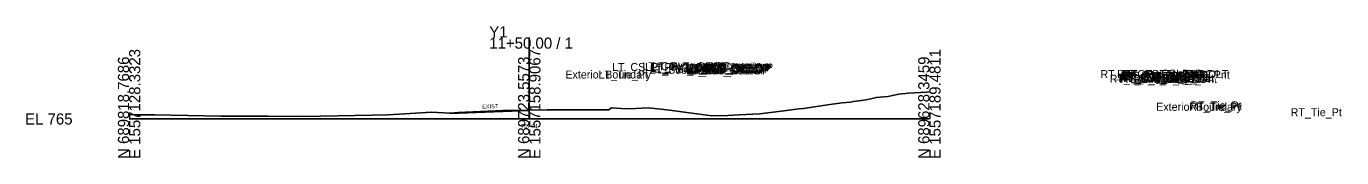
# Model space of a CAD drawing. Extents: x -26 to 303, y -10 to 5005.
# Drawn here: x -25.7 to 303, y 1490.3 to 1523.2 of the extents above; entities that cross this region are included whole.
import ezdxf

# ---------------------------------------------------------------- set-up
doc = ezdxf.new("R2010")
doc.units = 0
for name, color, linetype in [('Default', 7, 'Continuous'), ('Exist Cross Section Cell', 7, 'Continuous'), ('Exist XS Center Line Elevation Label', 7, 'Continuous'), ('Exist XS Ground Line', 7, 'Continuous'), ('Prop CMT Pvmt Course 1', 7, 'Continuous'), ('Prop CMT Pvmt Surface', 7, 'Continuous'), ('Prop XS SE Text', 7, 'Continuous')]:
    doc.layers.add(name, color=color, linetype=linetype)

msp = doc.modelspace()

# ---------------------------------------------------------------- linework, layer by layer
at = {"layer": 'Exist Cross Section Cell'}
for p, q in [((100, 1500), (100, 1520.37)), ((0, 1500), (100, 1500)), ((100, 1500), (200, 1500))]:
    msp.add_line(p, q, dxfattribs=at)
at = {"layer": 'Exist XS Ground Line'}
msp.add_lwpolyline([(0, 1501.08), (1.84, 1501.07), (3.01, 1501.07), (6.4, 1501), (22.89, 1500.72), (34.77, 1500.7), (43.56, 1500.61), (60.66, 1500.97), (64.57, 1501), (67.56, 1501.18), (75.54, 1501.67), (80.14, 1501.48), (82.23, 1501.65), (93.39, 1502.08), (93.84, 1502.1), (100, 1502.21), (104.44, 1502.28), (105.78, 1502.31), (118.02, 1502.3), (118.86, 1502.3), (119.88, 1502.3), (120.53, 1502.77), (124.21, 1502.57), (126.57, 1502.65), (129.69, 1502.81), (133.66, 1502.36), (135.67, 1502.14), (139.37, 1501.62), (145.59, 1500.74), (149.64, 1500.88), (152.45, 1501.06), (157.63, 1501.27), (164.28, 1502.14), (167.39, 1502.57), (168.56, 1502.64), (175.13, 1503.58), (178.19, 1504.02), (180.29, 1504.23), (181.02, 1504.37), (183.01, 1504.62), (184.62, 1504.88), (186.74, 1505.37), (188.61, 1505.55), (189.67, 1505.63), (190.77, 1505.9), (192.39, 1506.23), (193.11, 1506.3), (193.99, 1506.33), (194.81, 1506.43), (199.35, 1506.71), (200, 1506.79)], dxfattribs=at)
at = {"layer": 'Prop CMT Pvmt Course 1'}
for p, q in [((80.14, 1501.35), (100, 1502.08)), ((80.14, 1501.48), (80.14, 1501.35))]:
    msp.add_line(p, q, dxfattribs=at)
for points in [[(100, 1502.21), (100, 1502.08)], [(100, 1502.08), (100, 1502.21)]]:
    msp.add_lwpolyline(points, dxfattribs=at)
at = {"layer": 'Prop CMT Pvmt Surface'}
msp.add_line((80.14, 1501.48), (100, 1502.21), dxfattribs=at)

# ---------------------------------------------------------------- texts
at = {"layer": 'Default'}
for s, height, p in [('Exterior Boundary', 2, (109.02, 1510.11)), ('LT_Tie_Pt', 2, (117.32, 1510.11)), ('LT_CSLP_Pnt', 2, (120.67, 1511.99)), ('LT_CG_Top_BOC', 2, (128.28, 1512.18)), ('LT_Sub_OEOT', 2, (130.08, 1511.3)), ('LT_PV2_OEOT', 2, (130.17, 1511.93)), ('LT_PV3_OEOT', 2, (130.17, 1511.68)), ('LT_PV1_OEOT', 2, (130.74, 1512.18)), ('RT_Sub_OEEOP', 2, (139.17, 1511.15)), ('LT_Sub_OEEOP', 2, (139.21, 1511.15)), ('RT_PV2_OEEOP', 2, (139.26, 1511.78)), ('RT_PV3_OEEOP', 2, (139.26, 1511.53)), ('LT_PV2_OEEOP', 2, (139.31, 1511.78)), ('LT_PV3_OEEOP', 2, (139.31, 1511.53)), ('RT_PV1_OEEOP', 2, (139.83, 1511.9)), ('LT_PV1_OEEOP', 2, (139.87, 1511.9)), ('RT_PV2_IEEOP', 2, (139.91, 1511.78)), ('LT_PV2_IEEOP', 2, (139.95, 1511.78)), ('RT_PV1_IEEOP', 2, (140.47, 1511.9)), ('LT_PV1_IEEOP', 2, (140.52, 1511.9)), ('RT_PV2_PGL', 2, (141.17, 1511.78)), ('LT_PV2_PGL', 2, (141.21, 1511.78)), ('RT_PV1_PGL', 2, (141.73, 1512.03)), ('LT_PV1_PGL', 2, (141.78, 1512.03)), ('RT_Sub_Trench_Out_DLT', 2, (242.73, 1510.21)), ('RT_CG_Top_Face', 2, (246.93, 1510.25)), ('RT_CG_Top_BOC', 2, (248.45, 1510.25)), ('CSLP_Pnt', 2, (257.92, 1510.33)), ('RT_Sub_OEOT_CG', 2, (245.04, 1509.04)), ('RT_CG1_Shelf_Out', 2, (247.22, 1509.23)), ('RT_CG_Bot_IE', 2, (247.58, 1509.29)), ('RT_Sub_OEOT', 2, (247.75, 1509)), ('RT_PV2_OEOT', 2, (247.84, 1509.62)), ('RT_PV3_OEOT', 2, (247.84, 1509.37)), ('RT_CG_Top_Gut', 2, (247.91, 1509.75)), ('RT_PV1_OEOT', 2, (248.41, 1509.87)), ('RT_CG_Bot_BOC', 2, (248.49, 1509.24)), ('RT_Sub_OEOP', 2, (251.04, 1508.97)), ('CSLP_Pnt', 2, (259.38, 1508.99)), ('CSLP_Pnt', 2, (262.58, 1510.06)), ('Exterior Boundary', 2, (256.67, 1502.04)), ('RT_Tie_Pt', 2, (264.92, 1502.04)), ('RT_Tie_Pt', 2, (265.24, 1502.37)), ('RT_Tie_Pt', 2, (290.27, 1500.68)), ('-', 0.0001, (0, 1500))]:
    msp.add_text(s, height=height, dxfattribs=at).set_placement(p)
at = {"layer": 'Exist Cross Section Cell'}
for s, p in [('Y1', (90, 1520.37)), ('11+50.00 / 1', (90, 1517.57)), ('EL 765', (-26, 1498.6))]:
    msp.add_text(s, height=2.8, dxfattribs=at).set_placement(p)
for s, p in [('N 689818.7686', (0, 1490)), ('E 1557128.3323', (2.8, 1490)), ('N 689723.5573', (100, 1490)), ('E 1557158.9067', (102.8, 1490)), ('N 689628.3459', (200, 1490)), ('E 1557189.4811', (202.8, 1490))]:
    msp.add_text(s, height=2.8, rotation=90, dxfattribs=at).set_placement(p)
at = {"layer": 'Exist XS Center Line Elevation Label'}
msp.add_text('767.21', height=1, dxfattribs=at).set_placement((97.97, 1497.71))
at = {"layer": 'Prop XS SE Text'}
msp.add_text('EXIST', height=1, rotation=2.1078, dxfattribs=at).set_placement((88.26, 1502.57))

doc.saveas('drawing.dxf')
